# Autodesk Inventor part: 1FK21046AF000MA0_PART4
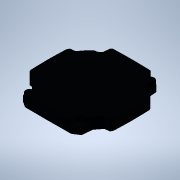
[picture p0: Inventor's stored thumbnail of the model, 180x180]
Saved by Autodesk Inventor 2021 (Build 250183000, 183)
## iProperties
Created: 2025-04
Part Number: 1FK21046AF000MA0_PART4
Material: Generic
Catalog Web Link: www.3dfindit.com
Description: -Servo synchronous motor
Document SubType Name: Modeling
Designer: psAdmin
Mass: 55.5405 g
Surface Area: 149.572 cm^2
Volume: 55.5405 cm^3
Density: 1 g/cm^3
Appearance: PSOLRGB-38-46-56
Category: PARTsolutions
Title: 1FK21046AF000MA0_PART4
Author: Cadenas PARTsolutions
Comments: Servo synchronous motor
Sending System: PARTsolutions
Preprocessor: ST-DEVELOPER v19.3
PSOL_IDENT_0: {$CADENAS_DATA/23d-libs/siemens_ag/_cat_/1c/1f/1fk21046af000ma0.prj},213 {VTYP=3D},{NB=1FK21046AF000
PSOL_IDENT_1: MA0_PART4},{LINA=1FK21046AF000MA0_PART4},{NN=1FK21046AF000MA0_PART4},{NOPRJ=TRUE},{DATE=19.08.2025 1
PSOL_IDENT_2: 4:00:28},{GEOMDATE=30.07.2025 02:02:08},{VERSION=},{LINEID=10},{WBVAR=},{WBNUMERIC=}  {NB=1FK21046AF
PSOL_IDENT_3: 000MA0_PART4},{LINA=1FK21046AF000MA0_PART4},{KT=DUMMY},{PREVIEW=../../../_pool_/cb/72/p_d211_xx_0043
PSOL_IDENT_4: 4j.png},{DESCSHORT=SIMOTICS S-1FK2 HD, SINAMICS S210 3AC 400V-480V, 3.2 Nm, 3000 rpm},{DESCLONG=SIMO
PSOL_IDENT_5: TICS S-1FK2 HD servo motor M0=3.2 Nm; PN = 1 kW at nN=3000 rpm (380-480 V); PN = 0.5 kW at nN=1500 r
PSOL_IDENT_6: pm (200-240 V); degree of protection IP64; cylindrical shaft D19x40mm; absolute encoder 22-bit + 12-
PSOL_IDENT_7: bit multiturn (encoder AM22DQC); with OCC interface; plug size M17, rotatable; SIMOTICS S-1FK2 servo
PSOL_IDENT_8: motorfor a wide range of uses in industrial environments. SIMOTICS S‑1FK2 servomotors are compact sy
PSOL_IDENT_9: nchronous motors with a high dynamic performance that set themselves apart as a result of their high
PSOL_IDENT_10: power density, degree of protection and overload capability. The motors are available in two varian
PSOL_IDENT_11: ts: as High Dynamic variant (highest dynamic performance as a result of the low intrinsic moment of
PSOL_IDENT_12: inertia for applications demanding a high dynamic performance with low moved masses) - and as Compac
PSOL_IDENT_13: t variant (precise and stable closed-loop control for medium up to large moved masses as a result of
PSOL_IDENT_14: a medium intrinsic moment of inertia). SIMOTICSS‑1FK2 servomotors fully exploit their strengths in
PSOL_IDENT_15: a system with the SINAMICSS210 frequency converter and simple connection using the one cable connect
PSOL_IDENT_16: ion (OCC). Advantages include the short control and positioning times, fast and precise correction o
PSOL_IDENT_17: f disturbing quantities as well as stable control with a high dynamic performance. The servo motors
PSOL_IDENT_18: can be configured to address a wide range of requirements. For example with and without holding brak
PSOL_IDENT_19: e, IP64 or IP65 degree of protection, singleturn or multiturn absolute encoders - to name just a few
PSOL_IDENT_20: . Further, the servomotors are available in different shaft heights extending from 20 to 100. A shaf
PSOL_IDENT_21: t sealing ring is available to achieve an IP65 degree of protection and for subsequent mounting at t
PSOL_IDENT_22: he motor or as spare part. SIMOTICS - the optimum motor for each and every motion control applicatio
PSOL_IDENT_23: n.},{INTNO=195125049666},{SUPPLIERALTNO=1FK2104-6AF00-0MA0},{MANUID=1FK21046AF000MA0},{MANUNAME=Siem
PSOL_IDENT_24: ens},{MANUTYPEDESC=Synchronous motor 1FK2-HD 3.2 NM},{AAU732=SIMOTICS},{AAO057=S-1FK2},{AAU734=SIMOT
PSOL_IDENT_25: ICS S-1FK2 HD servo motor M0=3.2 Nm; PN = 1 kW at nN=3000 rpm (380-480 V); PN = 0.5 kW at nN=1500 rp
PSOL_IDENT_26: m (200-240 V); degree of protection IP64; cylindrical shaft D19x40mm; absolute encoder 22-bit + 12-b
PSOL_IDENT_27: it multiturn (encoder AM22DQC); with OCC interface; plug size M17, rotatable;},{AAW338=Synchronous m
PSOL_IDENT_28: otor 1FK2-HD 3.2 NM},{AAO742=SIMOTICS},{AAO663=4042948694374},{NOCUPEROU=1},{PRICEQUANTITY=1},{QUANT
PSOL_IDENT_29: ITYMIN=1},{QUANTITYINT=1},{CTN=85015220},{COO=DE},{AAO676=1FK2104-6AF00-0MA0},{AAO677=Siemens AG},{O
PSOL_IDENT_30: RDERUNIT=C62},{CONTENTUNIT=C62}
NB: 1FK21046AF000MA0_PART4
NT: Servo synchronous motor
NBSYN: $MANUID._PART4
LINA: 1FK21046AF000MA0_PART4
CATALOG: SIEMENS
PREVIEW: ../../../_pool_/cb/72/p_d211_xx_00434j.png
DESCSHORT: SIMOTICS S-1FK2 HD, SINAMICS S210 3AC 400V-480V, 3.2 Nm, 3000 rpm
DESCLONG: SIMOTICS S-1FK2 HD servo motor M0=3.2 Nm; PN = 1 kW at nN=3000 rpm (380-480 V); PN = 0.5 kW at nN=1500 rpm (200-240 V); degree of protection IP64; cylindrical s
INTNO: 195125049666
SUPPLIERALTNO: 1FK2104-6AF00-0MA0
MANUID: 1FK21046AF000MA0
MANUNAME: Siemens
MANUTYPEDESC: Synchronous motor 1FK2-HD 3.2 NM
AAU732: SIMOTICS
AAO057: S-1FK2
AAU734: SIMOTICS S-1FK2 HD servo motor M0=3.2 Nm; PN = 1 kW at nN=3000 rpm (380-480 V); PN = 0.5 kW at nN=1500 rpm (200-240 V); degree of protection IP64; cylindrical s
AAW338: Synchronous motor 1FK2-HD 3.2 NM
AAO742: SIMOTICS
AAO663: 4042948694374.0
NOCUPEROU: 1
PRICEQUANTITY: 1
QUANTITYMIN: 1
QUANTITYINT: 1
CTN: 85015220
COO: DE
ARTICLENO: 1FK21046AF000MA0_PART4
BOMINFO: 1FK21046AF000MA0_PART4
CREATOR: CADENAS GmbH
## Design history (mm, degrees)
feature "2025_04_17_15_39_11_0331"
body "Solid1"
